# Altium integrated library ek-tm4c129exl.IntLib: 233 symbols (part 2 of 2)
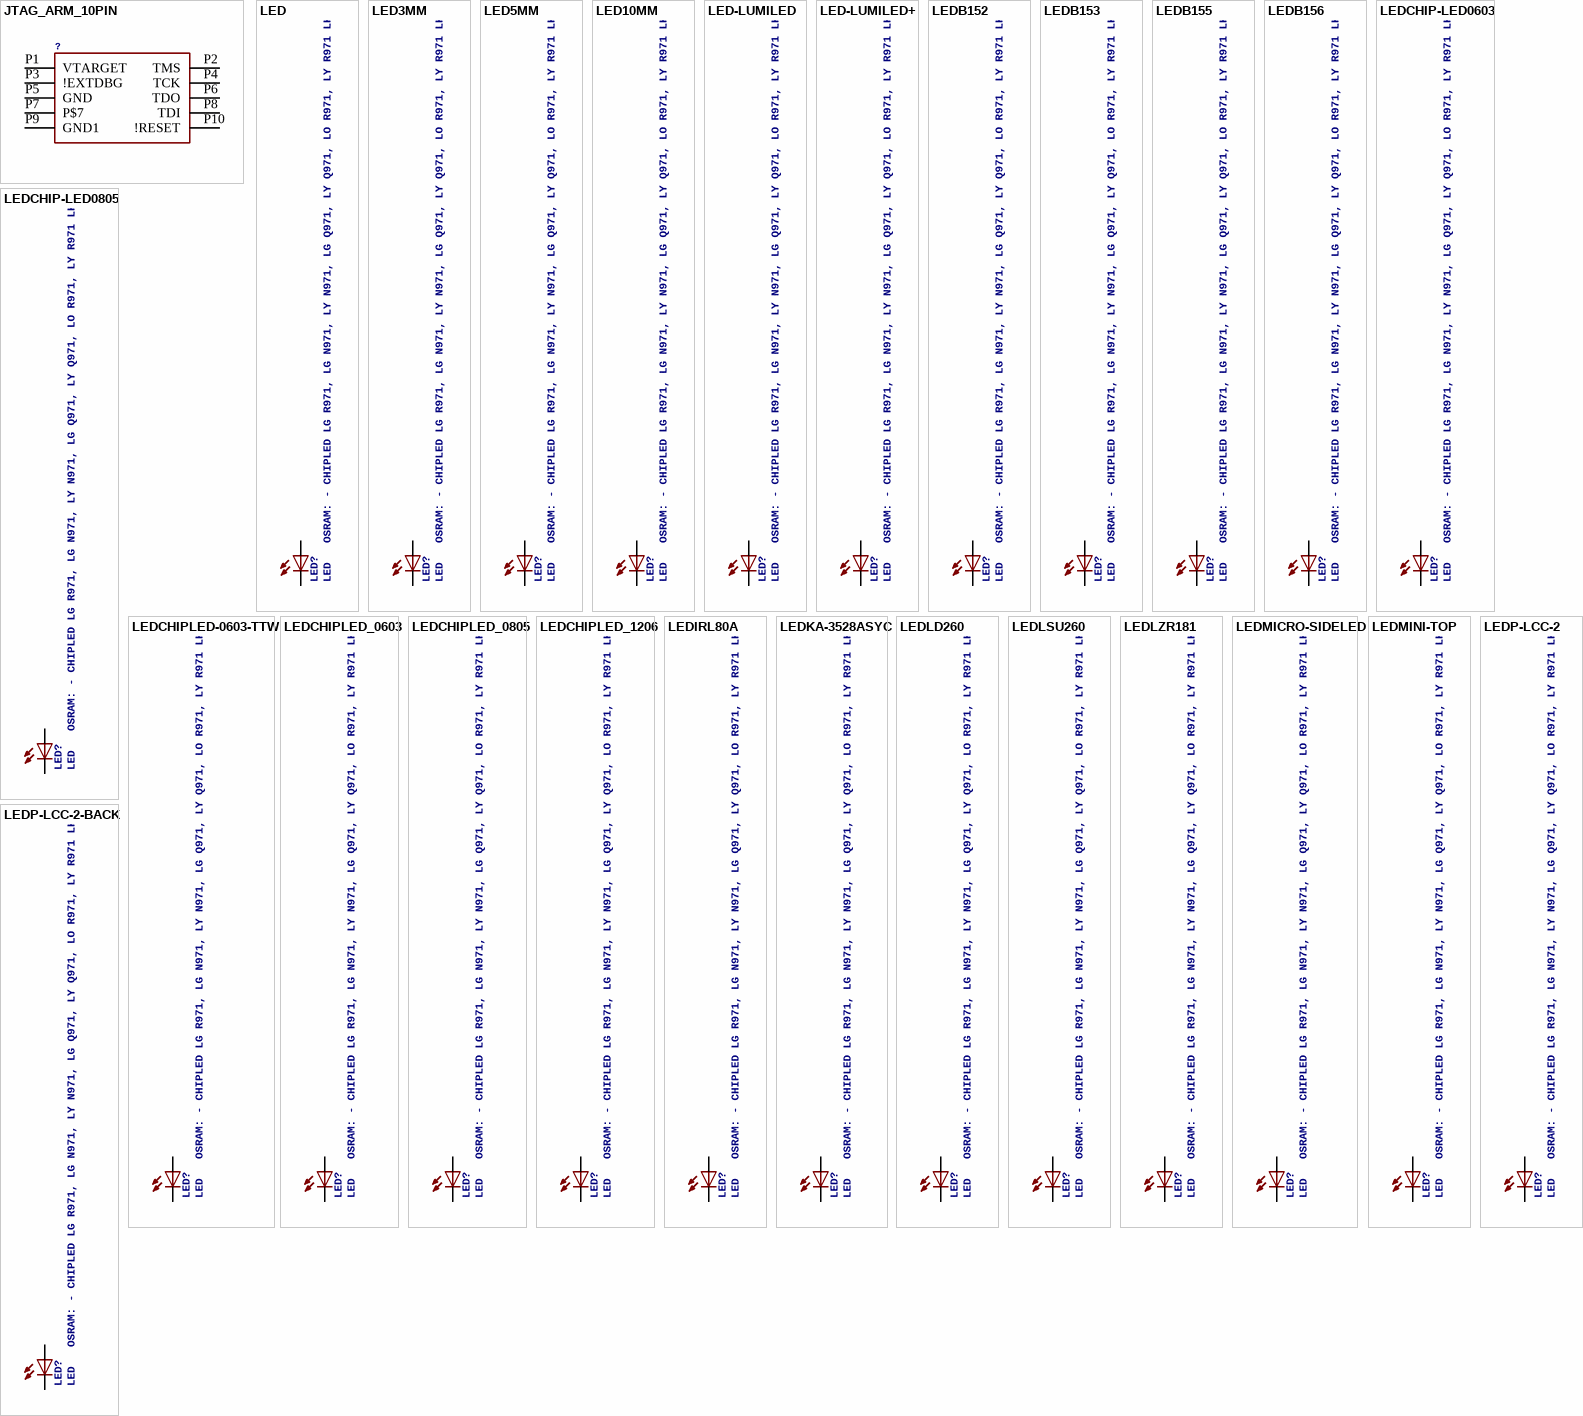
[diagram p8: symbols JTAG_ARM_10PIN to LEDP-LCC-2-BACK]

## LEDMICRO-SIDELED
designator LED?, comment LED   OSRAM: - CHIPLED LG R971, LG N971, LY N971, LG Q971, LY Q971, LO R971, LY R971 LH N974, LH R974 LS Q976, LO Q976, LY Q976 LO Q996 - Hyper CHIPLED LW Q18S LB Q993, LB Q99A, LB R99A - SideLED LS A670, LO A670, LY A670, LG A670, LP A670 LB A673, LV A673, LT A673, LW A673 LH A674 LY A675 LS A676, LA A676, LO A676, LY A676, LW A676 LS A679, LY A679, LG A679 -  Hyper Micro SIDELEDÂ® LS Y876, LA Y876, LO Y876, LY Y876 LT Y87S - SmartLED LW L88C, LW L88S LB L89C, LB L89S, LG L890 LS L89K, LO L89K, LY L89K LS L896, LA L896, LO L896, LY L896 - TOPLED LS T670, LO T670, LY T670, LG T670, LP T670 LSG T670, LSP T670, LSY T670, LOP T670, LYG T670 LG T671, LOG T671, LSG T671 LB T673, LV T673, LT T673, LW T673 LH T674 LS T676, LA T676, LO T676, LY T676, LB T676, LH T676, LSB T676, LW T676 LB T67C, LV T67C, LT T67C, LS T67K, LO T67K, LY T67K, LW E67C LS E67B, LA E67B, LO E67B, LY E67B, LB E67C, LV E67C, LT E67C LW T67C LS T679, LY T679, LG T679 LS T770, LO T770, LY T770, LG T770, LP T770 LB T773, LV T773, LT T773, LW T773 LH T774 LS E675, LA E675, LY E675, LS T675 LS T776, LA T776, LO T776, LY T776, LB T776 LHGB T686 LT T68C, LB T68C - Hyper Mini TOPLEDÂ® LB M676 - Mini TOPLED SantanaÂ® LG M470 LS M47K, LO M47K, LY M47K    Source: http://www.osram.convergy.de   LUXEON: - LUMILEDÂ® LXK2-PW12-R00, LXK2-PW12-S00, LXK2-PW14-U00, LXK2-PW14-V00 LXK2-PM12-R00, LXK2-PM12-S00, LXK2-PM14-U00 LXK2-PE12-Q00, LXK2-PE12-R00, LXK2-PE12-S00, LXK2-PE14-T00, LXK2-PE14-U00 LXK2-PB12-K00, LXK2-PB12-L00, LXK2-PB12-M00, LXK2-PB14-N00, LXK2-PB14-P00, LXK2-PB14-Q00 LXK2-PR12-L00, LXK2-PR12-M00, LXK2-PR14-Q00, LXK2-PR14-R00 LXK2-PD12-Q00, LXK2-PD12-R00, LXK2-PD12-S00 LXK2-PH12-R00, LXK2-PH12-S00 LXK2-PL12-P00, LXK2-PL12-Q00, LXK2-PL12-R00    Source: www.luxeon.com   KINGBRIGHT:   KA-3528ASYC Source: www.kingbright.com
footprint MICRO-SIDELED
pins: A, C

## LEDMINI-TOP
designator LED?, comment LED   OSRAM: - CHIPLED LG R971, LG N971, LY N971, LG Q971, LY Q971, LO R971, LY R971 LH N974, LH R974 LS Q976, LO Q976, LY Q976 LO Q996 - Hyper CHIPLED LW Q18S LB Q993, LB Q99A, LB R99A - SideLED LS A670, LO A670, LY A670, LG A670, LP A670 LB A673, LV A673, LT A673, LW A673 LH A674 LY A675 LS A676, LA A676, LO A676, LY A676, LW A676 LS A679, LY A679, LG A679 -  Hyper Micro SIDELEDÂ® LS Y876, LA Y876, LO Y876, LY Y876 LT Y87S - SmartLED LW L88C, LW L88S LB L89C, LB L89S, LG L890 LS L89K, LO L89K, LY L89K LS L896, LA L896, LO L896, LY L896 - TOPLED LS T670, LO T670, LY T670, LG T670, LP T670 LSG T670, LSP T670, LSY T670, LOP T670, LYG T670 LG T671, LOG T671, LSG T671 LB T673, LV T673, LT T673, LW T673 LH T674 LS T676, LA T676, LO T676, LY T676, LB T676, LH T676, LSB T676, LW T676 LB T67C, LV T67C, LT T67C, LS T67K, LO T67K, LY T67K, LW E67C LS E67B, LA E67B, LO E67B, LY E67B, LB E67C, LV E67C, LT E67C LW T67C LS T679, LY T679, LG T679 LS T770, LO T770, LY T770, LG T770, LP T770 LB T773, LV T773, LT T773, LW T773 LH T774 LS E675, LA E675, LY E675, LS T675 LS T776, LA T776, LO T776, LY T776, LB T776 LHGB T686 LT T68C, LB T68C - Hyper Mini TOPLEDÂ® LB M676 - Mini TOPLED SantanaÂ® LG M470 LS M47K, LO M47K, LY M47K    Source: http://www.osram.convergy.de   LUXEON: - LUMILEDÂ® LXK2-PW12-R00, LXK2-PW12-S00, LXK2-PW14-U00, LXK2-PW14-V00 LXK2-PM12-R00, LXK2-PM12-S00, LXK2-PM14-U00 LXK2-PE12-Q00, LXK2-PE12-R00, LXK2-PE12-S00, LXK2-PE14-T00, LXK2-PE14-U00 LXK2-PB12-K00, LXK2-PB12-L00, LXK2-PB12-M00, LXK2-PB14-N00, LXK2-PB14-P00, LXK2-PB14-Q00 LXK2-PR12-L00, LXK2-PR12-M00, LXK2-PR14-Q00, LXK2-PR14-R00 LXK2-PD12-Q00, LXK2-PD12-R00, LXK2-PD12-S00 LXK2-PH12-R00, LXK2-PH12-S00 LXK2-PL12-P00, LXK2-PL12-Q00, LXK2-PL12-R00    Source: www.luxeon.com   KINGBRIGHT:   KA-3528ASYC Source: www.kingbright.com
footprint OSRAM-MINI-TOP-LED
pins: A, C

## LEDP-LCC-2
designator LED?, comment LED   OSRAM: - CHIPLED LG R971, LG N971, LY N971, LG Q971, LY Q971, LO R971, LY R971 LH N974, LH R974 LS Q976, LO Q976, LY Q976 LO Q996 - Hyper CHIPLED LW Q18S LB Q993, LB Q99A, LB R99A - SideLED LS A670, LO A670, LY A670, LG A670, LP A670 LB A673, LV A673, LT A673, LW A673 LH A674 LY A675 LS A676, LA A676, LO A676, LY A676, LW A676 LS A679, LY A679, LG A679 -  Hyper Micro SIDELEDÂ® LS Y876, LA Y876, LO Y876, LY Y876 LT Y87S - SmartLED LW L88C, LW L88S LB L89C, LB L89S, LG L890 LS L89K, LO L89K, LY L89K LS L896, LA L896, LO L896, LY L896 - TOPLED LS T670, LO T670, LY T670, LG T670, LP T670 LSG T670, LSP T670, LSY T670, LOP T670, LYG T670 LG T671, LOG T671, LSG T671 LB T673, LV T673, LT T673, LW T673 LH T674 LS T676, LA T676, LO T676, LY T676, LB T676, LH T676, LSB T676, LW T676 LB T67C, LV T67C, LT T67C, LS T67K, LO T67K, LY T67K, LW E67C LS E67B, LA E67B, LO E67B, LY E67B, LB E67C, LV E67C, LT E67C LW T67C LS T679, LY T679, LG T679 LS T770, LO T770, LY T770, LG T770, LP T770 LB T773, LV T773, LT T773, LW T773 LH T774 LS E675, LA E675, LY E675, LS T675 LS T776, LA T776, LO T776, LY T776, LB T776 LHGB T686 LT T68C, LB T68C - Hyper Mini TOPLEDÂ® LB M676 - Mini TOPLED SantanaÂ® LG M470 LS M47K, LO M47K, LY M47K    Source: http://www.osram.convergy.de   LUXEON: - LUMILEDÂ® LXK2-PW12-R00, LXK2-PW12-S00, LXK2-PW14-U00, LXK2-PW14-V00 LXK2-PM12-R00, LXK2-PM12-S00, LXK2-PM14-U00 LXK2-PE12-Q00, LXK2-PE12-R00, LXK2-PE12-S00, LXK2-PE14-T00, LXK2-PE14-U00 LXK2-PB12-K00, LXK2-PB12-L00, LXK2-PB12-M00, LXK2-PB14-N00, LXK2-PB14-P00, LXK2-PB14-Q00 LXK2-PR12-L00, LXK2-PR12-M00, LXK2-PR14-Q00, LXK2-PR14-R00 LXK2-PD12-Q00, LXK2-PD12-R00, LXK2-PD12-S00 LXK2-PH12-R00, LXK2-PH12-S00 LXK2-PL12-P00, LXK2-PL12-Q00, LXK2-PL12-R00    Source: www.luxeon.com   KINGBRIGHT:   KA-3528ASYC Source: www.kingbright.com
footprint P-LCC-2
pins: A, C

## LEDP-LCC-2-BACK
designator LED?, comment LED   OSRAM: - CHIPLED LG R971, LG N971, LY N971, LG Q971, LY Q971, LO R971, LY R971 LH N974, LH R974 LS Q976, LO Q976, LY Q976 LO Q996 - Hyper CHIPLED LW Q18S LB Q993, LB Q99A, LB R99A - SideLED LS A670, LO A670, LY A670, LG A670, LP A670 LB A673, LV A673, LT A673, LW A673 LH A674 LY A675 LS A676, LA A676, LO A676, LY A676, LW A676 LS A679, LY A679, LG A679 -  Hyper Micro SIDELEDÂ® LS Y876, LA Y876, LO Y876, LY Y876 LT Y87S - SmartLED LW L88C, LW L88S LB L89C, LB L89S, LG L890 LS L89K, LO L89K, LY L89K LS L896, LA L896, LO L896, LY L896 - TOPLED LS T670, LO T670, LY T670, LG T670, LP T670 LSG T670, LSP T670, LSY T670, LOP T670, LYG T670 LG T671, LOG T671, LSG T671 LB T673, LV T673, LT T673, LW T673 LH T674 LS T676, LA T676, LO T676, LY T676, LB T676, LH T676, LSB T676, LW T676 LB T67C, LV T67C, LT T67C, LS T67K, LO T67K, LY T67K, LW E67C LS E67B, LA E67B, LO E67B, LY E67B, LB E67C, LV E67C, LT E67C LW T67C LS T679, LY T679, LG T679 LS T770, LO T770, LY T770, LG T770, LP T770 LB T773, LV T773, LT T773, LW T773 LH T774 LS E675, LA E675, LY E675, LS T675 LS T776, LA T776, LO T776, LY T776, LB T776 LHGB T686 LT T68C, LB T68C - Hyper Mini TOPLEDÂ® LB M676 - Mini TOPLED SantanaÂ® LG M470 LS M47K, LO M47K, LY M47K    Source: http://www.osram.convergy.de   LUXEON: - LUMILEDÂ® LXK2-PW12-R00, LXK2-PW12-S00, LXK2-PW14-U00, LXK2-PW14-V00 LXK2-PM12-R00, LXK2-PM12-S00, LXK2-PM14-U00 LXK2-PE12-Q00, LXK2-PE12-R00, LXK2-PE12-S00, LXK2-PE14-T00, LXK2-PE14-U00 LXK2-PB12-K00, LXK2-PB12-L00, LXK2-PB12-M00, LXK2-PB14-N00, LXK2-PB14-P00, LXK2-PB14-Q00 LXK2-PR12-L00, LXK2-PR12-M00, LXK2-PR14-Q00, LXK2-PR14-R00 LXK2-PD12-Q00, LXK2-PD12-R00, LXK2-PD12-S00 LXK2-PH12-R00, LXK2-PH12-S00 LXK2-PL12-P00, LXK2-PL12-Q00, LXK2-PL12-R00    Source: www.luxeon.com   KINGBRIGHT:   KA-3528ASYC Source: www.kingbright.com
footprint P-LCC-2-TOPLED-RG
pins: A, C

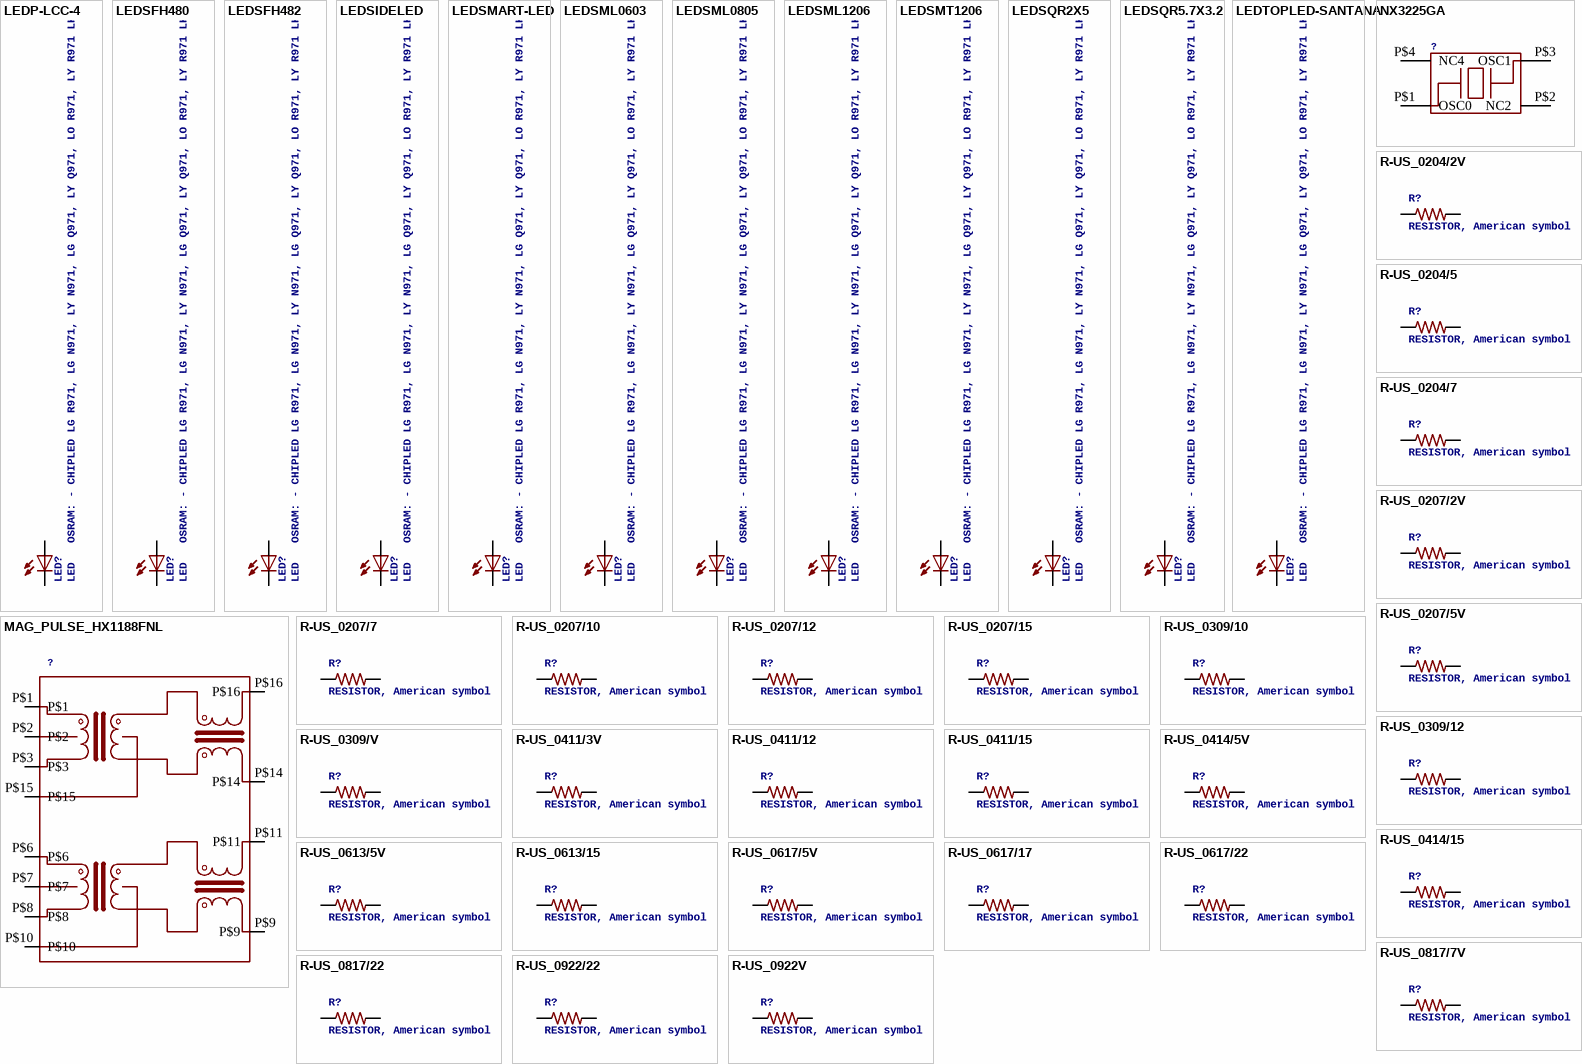
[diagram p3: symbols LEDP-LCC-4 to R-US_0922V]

## LEDP-LCC-4
designator LED?, comment LED   OSRAM: - CHIPLED LG R971, LG N971, LY N971, LG Q971, LY Q971, LO R971, LY R971 LH N974, LH R974 LS Q976, LO Q976, LY Q976 LO Q996 - Hyper CHIPLED LW Q18S LB Q993, LB Q99A, LB R99A - SideLED LS A670, LO A670, LY A670, LG A670, LP A670 LB A673, LV A673, LT A673, LW A673 LH A674 LY A675 LS A676, LA A676, LO A676, LY A676, LW A676 LS A679, LY A679, LG A679 -  Hyper Micro SIDELEDÂ® LS Y876, LA Y876, LO Y876, LY Y876 LT Y87S - SmartLED LW L88C, LW L88S LB L89C, LB L89S, LG L890 LS L89K, LO L89K, LY L89K LS L896, LA L896, LO L896, LY L896 - TOPLED LS T670, LO T670, LY T670, LG T670, LP T670 LSG T670, LSP T670, LSY T670, LOP T670, LYG T670 LG T671, LOG T671, LSG T671 LB T673, LV T673, LT T673, LW T673 LH T674 LS T676, LA T676, LO T676, LY T676, LB T676, LH T676, LSB T676, LW T676 LB T67C, LV T67C, LT T67C, LS T67K, LO T67K, LY T67K, LW E67C LS E67B, LA E67B, LO E67B, LY E67B, LB E67C, LV E67C, LT E67C LW T67C LS T679, LY T679, LG T679 LS T770, LO T770, LY T770, LG T770, LP T770 LB T773, LV T773, LT T773, LW T773 LH T774 LS E675, LA E675, LY E675, LS T675 LS T776, LA T776, LO T776, LY T776, LB T776 LHGB T686 LT T68C, LB T68C - Hyper Mini TOPLEDÂ® LB M676 - Mini TOPLED SantanaÂ® LG M470 LS M47K, LO M47K, LY M47K    Source: http://www.osram.convergy.de   LUXEON: - LUMILEDÂ® LXK2-PW12-R00, LXK2-PW12-S00, LXK2-PW14-U00, LXK2-PW14-V00 LXK2-PM12-R00, LXK2-PM12-S00, LXK2-PM14-U00 LXK2-PE12-Q00, LXK2-PE12-R00, LXK2-PE12-S00, LXK2-PE14-T00, LXK2-PE14-U00 LXK2-PB12-K00, LXK2-PB12-L00, LXK2-PB12-M00, LXK2-PB14-N00, LXK2-PB14-P00, LXK2-PB14-Q00 LXK2-PR12-L00, LXK2-PR12-M00, LXK2-PR14-Q00, LXK2-PR14-R00 LXK2-PD12-Q00, LXK2-PD12-R00, LXK2-PD12-S00 LXK2-PH12-R00, LXK2-PH12-S00 LXK2-PL12-P00, LXK2-PL12-Q00, LXK2-PL12-R00    Source: www.luxeon.com   KINGBRIGHT:   KA-3528ASYC Source: www.kingbright.com
footprint P-LCC-4
pins: A, C@4 C

## LEDSFH480
designator LED?, comment LED   OSRAM: - CHIPLED LG R971, LG N971, LY N971, LG Q971, LY Q971, LO R971, LY R971 LH N974, LH R974 LS Q976, LO Q976, LY Q976 LO Q996 - Hyper CHIPLED LW Q18S LB Q993, LB Q99A, LB R99A - SideLED LS A670, LO A670, LY A670, LG A670, LP A670 LB A673, LV A673, LT A673, LW A673 LH A674 LY A675 LS A676, LA A676, LO A676, LY A676, LW A676 LS A679, LY A679, LG A679 -  Hyper Micro SIDELEDÂ® LS Y876, LA Y876, LO Y876, LY Y876 LT Y87S - SmartLED LW L88C, LW L88S LB L89C, LB L89S, LG L890 LS L89K, LO L89K, LY L89K LS L896, LA L896, LO L896, LY L896 - TOPLED LS T670, LO T670, LY T670, LG T670, LP T670 LSG T670, LSP T670, LSY T670, LOP T670, LYG T670 LG T671, LOG T671, LSG T671 LB T673, LV T673, LT T673, LW T673 LH T674 LS T676, LA T676, LO T676, LY T676, LB T676, LH T676, LSB T676, LW T676 LB T67C, LV T67C, LT T67C, LS T67K, LO T67K, LY T67K, LW E67C LS E67B, LA E67B, LO E67B, LY E67B, LB E67C, LV E67C, LT E67C LW T67C LS T679, LY T679, LG T679 LS T770, LO T770, LY T770, LG T770, LP T770 LB T773, LV T773, LT T773, LW T773 LH T774 LS E675, LA E675, LY E675, LS T675 LS T776, LA T776, LO T776, LY T776, LB T776 LHGB T686 LT T68C, LB T68C - Hyper Mini TOPLEDÂ® LB M676 - Mini TOPLED SantanaÂ® LG M470 LS M47K, LO M47K, LY M47K    Source: http://www.osram.convergy.de   LUXEON: - LUMILEDÂ® LXK2-PW12-R00, LXK2-PW12-S00, LXK2-PW14-U00, LXK2-PW14-V00 LXK2-PM12-R00, LXK2-PM12-S00, LXK2-PM14-U00 LXK2-PE12-Q00, LXK2-PE12-R00, LXK2-PE12-S00, LXK2-PE14-T00, LXK2-PE14-U00 LXK2-PB12-K00, LXK2-PB12-L00, LXK2-PB12-M00, LXK2-PB14-N00, LXK2-PB14-P00, LXK2-PB14-Q00 LXK2-PR12-L00, LXK2-PR12-M00, LXK2-PR14-Q00, LXK2-PR14-R00 LXK2-PD12-Q00, LXK2-PD12-R00, LXK2-PD12-S00 LXK2-PH12-R00, LXK2-PH12-S00 LXK2-PL12-P00, LXK2-PL12-Q00, LXK2-PL12-R00    Source: www.luxeon.com   KINGBRIGHT:   KA-3528ASYC Source: www.kingbright.com
footprint SFH480
pins: A, K C

## LEDSFH482
designator LED?, comment LED   OSRAM: - CHIPLED LG R971, LG N971, LY N971, LG Q971, LY Q971, LO R971, LY R971 LH N974, LH R974 LS Q976, LO Q976, LY Q976 LO Q996 - Hyper CHIPLED LW Q18S LB Q993, LB Q99A, LB R99A - SideLED LS A670, LO A670, LY A670, LG A670, LP A670 LB A673, LV A673, LT A673, LW A673 LH A674 LY A675 LS A676, LA A676, LO A676, LY A676, LW A676 LS A679, LY A679, LG A679 -  Hyper Micro SIDELEDÂ® LS Y876, LA Y876, LO Y876, LY Y876 LT Y87S - SmartLED LW L88C, LW L88S LB L89C, LB L89S, LG L890 LS L89K, LO L89K, LY L89K LS L896, LA L896, LO L896, LY L896 - TOPLED LS T670, LO T670, LY T670, LG T670, LP T670 LSG T670, LSP T670, LSY T670, LOP T670, LYG T670 LG T671, LOG T671, LSG T671 LB T673, LV T673, LT T673, LW T673 LH T674 LS T676, LA T676, LO T676, LY T676, LB T676, LH T676, LSB T676, LW T676 LB T67C, LV T67C, LT T67C, LS T67K, LO T67K, LY T67K, LW E67C LS E67B, LA E67B, LO E67B, LY E67B, LB E67C, LV E67C, LT E67C LW T67C LS T679, LY T679, LG T679 LS T770, LO T770, LY T770, LG T770, LP T770 LB T773, LV T773, LT T773, LW T773 LH T774 LS E675, LA E675, LY E675, LS T675 LS T776, LA T776, LO T776, LY T776, LB T776 LHGB T686 LT T68C, LB T68C - Hyper Mini TOPLEDÂ® LB M676 - Mini TOPLED SantanaÂ® LG M470 LS M47K, LO M47K, LY M47K    Source: http://www.osram.convergy.de   LUXEON: - LUMILEDÂ® LXK2-PW12-R00, LXK2-PW12-S00, LXK2-PW14-U00, LXK2-PW14-V00 LXK2-PM12-R00, LXK2-PM12-S00, LXK2-PM14-U00 LXK2-PE12-Q00, LXK2-PE12-R00, LXK2-PE12-S00, LXK2-PE14-T00, LXK2-PE14-U00 LXK2-PB12-K00, LXK2-PB12-L00, LXK2-PB12-M00, LXK2-PB14-N00, LXK2-PB14-P00, LXK2-PB14-Q00 LXK2-PR12-L00, LXK2-PR12-M00, LXK2-PR14-Q00, LXK2-PR14-R00 LXK2-PD12-Q00, LXK2-PD12-R00, LXK2-PD12-S00 LXK2-PH12-R00, LXK2-PH12-S00 LXK2-PL12-P00, LXK2-PL12-Q00, LXK2-PL12-R00    Source: www.luxeon.com   KINGBRIGHT:   KA-3528ASYC Source: www.kingbright.com
footprint SFH482
pins: A, K C

## LEDSIDELED
designator LED?, comment LED   OSRAM: - CHIPLED LG R971, LG N971, LY N971, LG Q971, LY Q971, LO R971, LY R971 LH N974, LH R974 LS Q976, LO Q976, LY Q976 LO Q996 - Hyper CHIPLED LW Q18S LB Q993, LB Q99A, LB R99A - SideLED LS A670, LO A670, LY A670, LG A670, LP A670 LB A673, LV A673, LT A673, LW A673 LH A674 LY A675 LS A676, LA A676, LO A676, LY A676, LW A676 LS A679, LY A679, LG A679 -  Hyper Micro SIDELEDÂ® LS Y876, LA Y876, LO Y876, LY Y876 LT Y87S - SmartLED LW L88C, LW L88S LB L89C, LB L89S, LG L890 LS L89K, LO L89K, LY L89K LS L896, LA L896, LO L896, LY L896 - TOPLED LS T670, LO T670, LY T670, LG T670, LP T670 LSG T670, LSP T670, LSY T670, LOP T670, LYG T670 LG T671, LOG T671, LSG T671 LB T673, LV T673, LT T673, LW T673 LH T674 LS T676, LA T676, LO T676, LY T676, LB T676, LH T676, LSB T676, LW T676 LB T67C, LV T67C, LT T67C, LS T67K, LO T67K, LY T67K, LW E67C LS E67B, LA E67B, LO E67B, LY E67B, LB E67C, LV E67C, LT E67C LW T67C LS T679, LY T679, LG T679 LS T770, LO T770, LY T770, LG T770, LP T770 LB T773, LV T773, LT T773, LW T773 LH T774 LS E675, LA E675, LY E675, LS T675 LS T776, LA T776, LO T776, LY T776, LB T776 LHGB T686 LT T68C, LB T68C - Hyper Mini TOPLEDÂ® LB M676 - Mini TOPLED SantanaÂ® LG M470 LS M47K, LO M47K, LY M47K    Source: http://www.osram.convergy.de   LUXEON: - LUMILEDÂ® LXK2-PW12-R00, LXK2-PW12-S00, LXK2-PW14-U00, LXK2-PW14-V00 LXK2-PM12-R00, LXK2-PM12-S00, LXK2-PM14-U00 LXK2-PE12-Q00, LXK2-PE12-R00, LXK2-PE12-S00, LXK2-PE14-T00, LXK2-PE14-U00 LXK2-PB12-K00, LXK2-PB12-L00, LXK2-PB12-M00, LXK2-PB14-N00, LXK2-PB14-P00, LXK2-PB14-Q00 LXK2-PR12-L00, LXK2-PR12-M00, LXK2-PR14-Q00, LXK2-PR14-R00 LXK2-PD12-Q00, LXK2-PD12-R00, LXK2-PD12-S00 LXK2-PH12-R00, LXK2-PH12-S00 LXK2-PL12-P00, LXK2-PL12-Q00, LXK2-PL12-R00    Source: www.luxeon.com   KINGBRIGHT:   KA-3528ASYC Source: www.kingbright.com
footprint OSRAM-SIDELED
pins: A, C

## LEDSMART-LED
designator LED?, comment LED   OSRAM: - CHIPLED LG R971, LG N971, LY N971, LG Q971, LY Q971, LO R971, LY R971 LH N974, LH R974 LS Q976, LO Q976, LY Q976 LO Q996 - Hyper CHIPLED LW Q18S LB Q993, LB Q99A, LB R99A - SideLED LS A670, LO A670, LY A670, LG A670, LP A670 LB A673, LV A673, LT A673, LW A673 LH A674 LY A675 LS A676, LA A676, LO A676, LY A676, LW A676 LS A679, LY A679, LG A679 -  Hyper Micro SIDELEDÂ® LS Y876, LA Y876, LO Y876, LY Y876 LT Y87S - SmartLED LW L88C, LW L88S LB L89C, LB L89S, LG L890 LS L89K, LO L89K, LY L89K LS L896, LA L896, LO L896, LY L896 - TOPLED LS T670, LO T670, LY T670, LG T670, LP T670 LSG T670, LSP T670, LSY T670, LOP T670, LYG T670 LG T671, LOG T671, LSG T671 LB T673, LV T673, LT T673, LW T673 LH T674 LS T676, LA T676, LO T676, LY T676, LB T676, LH T676, LSB T676, LW T676 LB T67C, LV T67C, LT T67C, LS T67K, LO T67K, LY T67K, LW E67C LS E67B, LA E67B, LO E67B, LY E67B, LB E67C, LV E67C, LT E67C LW T67C LS T679, LY T679, LG T679 LS T770, LO T770, LY T770, LG T770, LP T770 LB T773, LV T773, LT T773, LW T773 LH T774 LS E675, LA E675, LY E675, LS T675 LS T776, LA T776, LO T776, LY T776, LB T776 LHGB T686 LT T68C, LB T68C - Hyper Mini TOPLEDÂ® LB M676 - Mini TOPLED SantanaÂ® LG M470 LS M47K, LO M47K, LY M47K    Source: http://www.osram.convergy.de   LUXEON: - LUMILEDÂ® LXK2-PW12-R00, LXK2-PW12-S00, LXK2-PW14-U00, LXK2-PW14-V00 LXK2-PM12-R00, LXK2-PM12-S00, LXK2-PM14-U00 LXK2-PE12-Q00, LXK2-PE12-R00, LXK2-PE12-S00, LXK2-PE14-T00, LXK2-PE14-U00 LXK2-PB12-K00, LXK2-PB12-L00, LXK2-PB12-M00, LXK2-PB14-N00, LXK2-PB14-P00, LXK2-PB14-Q00 LXK2-PR12-L00, LXK2-PR12-M00, LXK2-PR14-Q00, LXK2-PR14-R00 LXK2-PD12-Q00, LXK2-PD12-R00, LXK2-PD12-S00 LXK2-PH12-R00, LXK2-PH12-S00 LXK2-PL12-P00, LXK2-PL12-Q00, LXK2-PL12-R00    Source: www.luxeon.com   KINGBRIGHT:   KA-3528ASYC Source: www.kingbright.com
footprint SMART-LED
pins: A, B C

## LEDSML0603
designator LED?, comment LED   OSRAM: - CHIPLED LG R971, LG N971, LY N971, LG Q971, LY Q971, LO R971, LY R971 LH N974, LH R974 LS Q976, LO Q976, LY Q976 LO Q996 - Hyper CHIPLED LW Q18S LB Q993, LB Q99A, LB R99A - SideLED LS A670, LO A670, LY A670, LG A670, LP A670 LB A673, LV A673, LT A673, LW A673 LH A674 LY A675 LS A676, LA A676, LO A676, LY A676, LW A676 LS A679, LY A679, LG A679 -  Hyper Micro SIDELEDÂ® LS Y876, LA Y876, LO Y876, LY Y876 LT Y87S - SmartLED LW L88C, LW L88S LB L89C, LB L89S, LG L890 LS L89K, LO L89K, LY L89K LS L896, LA L896, LO L896, LY L896 - TOPLED LS T670, LO T670, LY T670, LG T670, LP T670 LSG T670, LSP T670, LSY T670, LOP T670, LYG T670 LG T671, LOG T671, LSG T671 LB T673, LV T673, LT T673, LW T673 LH T674 LS T676, LA T676, LO T676, LY T676, LB T676, LH T676, LSB T676, LW T676 LB T67C, LV T67C, LT T67C, LS T67K, LO T67K, LY T67K, LW E67C LS E67B, LA E67B, LO E67B, LY E67B, LB E67C, LV E67C, LT E67C LW T67C LS T679, LY T679, LG T679 LS T770, LO T770, LY T770, LG T770, LP T770 LB T773, LV T773, LT T773, LW T773 LH T774 LS E675, LA E675, LY E675, LS T675 LS T776, LA T776, LO T776, LY T776, LB T776 LHGB T686 LT T68C, LB T68C - Hyper Mini TOPLEDÂ® LB M676 - Mini TOPLED SantanaÂ® LG M470 LS M47K, LO M47K, LY M47K    Source: http://www.osram.convergy.de   LUXEON: - LUMILEDÂ® LXK2-PW12-R00, LXK2-PW12-S00, LXK2-PW14-U00, LXK2-PW14-V00 LXK2-PM12-R00, LXK2-PM12-S00, LXK2-PM14-U00 LXK2-PE12-Q00, LXK2-PE12-R00, LXK2-PE12-S00, LXK2-PE14-T00, LXK2-PE14-U00 LXK2-PB12-K00, LXK2-PB12-L00, LXK2-PB12-M00, LXK2-PB14-N00, LXK2-PB14-P00, LXK2-PB14-Q00 LXK2-PR12-L00, LXK2-PR12-M00, LXK2-PR14-Q00, LXK2-PR14-R00 LXK2-PD12-Q00, LXK2-PD12-R00, LXK2-PD12-S00 LXK2-PH12-R00, LXK2-PH12-S00 LXK2-PL12-P00, LXK2-PL12-Q00, LXK2-PL12-R00    Source: www.luxeon.com   KINGBRIGHT:   KA-3528ASYC Source: www.kingbright.com
footprint SML0603
pins: A, C

## LEDSML0805
designator LED?, comment LED   OSRAM: - CHIPLED LG R971, LG N971, LY N971, LG Q971, LY Q971, LO R971, LY R971 LH N974, LH R974 LS Q976, LO Q976, LY Q976 LO Q996 - Hyper CHIPLED LW Q18S LB Q993, LB Q99A, LB R99A - SideLED LS A670, LO A670, LY A670, LG A670, LP A670 LB A673, LV A673, LT A673, LW A673 LH A674 LY A675 LS A676, LA A676, LO A676, LY A676, LW A676 LS A679, LY A679, LG A679 -  Hyper Micro SIDELEDÂ® LS Y876, LA Y876, LO Y876, LY Y876 LT Y87S - SmartLED LW L88C, LW L88S LB L89C, LB L89S, LG L890 LS L89K, LO L89K, LY L89K LS L896, LA L896, LO L896, LY L896 - TOPLED LS T670, LO T670, LY T670, LG T670, LP T670 LSG T670, LSP T670, LSY T670, LOP T670, LYG T670 LG T671, LOG T671, LSG T671 LB T673, LV T673, LT T673, LW T673 LH T674 LS T676, LA T676, LO T676, LY T676, LB T676, LH T676, LSB T676, LW T676 LB T67C, LV T67C, LT T67C, LS T67K, LO T67K, LY T67K, LW E67C LS E67B, LA E67B, LO E67B, LY E67B, LB E67C, LV E67C, LT E67C LW T67C LS T679, LY T679, LG T679 LS T770, LO T770, LY T770, LG T770, LP T770 LB T773, LV T773, LT T773, LW T773 LH T774 LS E675, LA E675, LY E675, LS T675 LS T776, LA T776, LO T776, LY T776, LB T776 LHGB T686 LT T68C, LB T68C - Hyper Mini TOPLEDÂ® LB M676 - Mini TOPLED SantanaÂ® LG M470 LS M47K, LO M47K, LY M47K    Source: http://www.osram.convergy.de   LUXEON: - LUMILEDÂ® LXK2-PW12-R00, LXK2-PW12-S00, LXK2-PW14-U00, LXK2-PW14-V00 LXK2-PM12-R00, LXK2-PM12-S00, LXK2-PM14-U00 LXK2-PE12-Q00, LXK2-PE12-R00, LXK2-PE12-S00, LXK2-PE14-T00, LXK2-PE14-U00 LXK2-PB12-K00, LXK2-PB12-L00, LXK2-PB12-M00, LXK2-PB14-N00, LXK2-PB14-P00, LXK2-PB14-Q00 LXK2-PR12-L00, LXK2-PR12-M00, LXK2-PR14-Q00, LXK2-PR14-R00 LXK2-PD12-Q00, LXK2-PD12-R00, LXK2-PD12-S00 LXK2-PH12-R00, LXK2-PH12-S00 LXK2-PL12-P00, LXK2-PL12-Q00, LXK2-PL12-R00    Source: www.luxeon.com   KINGBRIGHT:   KA-3528ASYC Source: www.kingbright.com
footprint SML0805
pins: A, C

## LEDSML1206
designator LED?, comment LED   OSRAM: - CHIPLED LG R971, LG N971, LY N971, LG Q971, LY Q971, LO R971, LY R971 LH N974, LH R974 LS Q976, LO Q976, LY Q976 LO Q996 - Hyper CHIPLED LW Q18S LB Q993, LB Q99A, LB R99A - SideLED LS A670, LO A670, LY A670, LG A670, LP A670 LB A673, LV A673, LT A673, LW A673 LH A674 LY A675 LS A676, LA A676, LO A676, LY A676, LW A676 LS A679, LY A679, LG A679 -  Hyper Micro SIDELEDÂ® LS Y876, LA Y876, LO Y876, LY Y876 LT Y87S - SmartLED LW L88C, LW L88S LB L89C, LB L89S, LG L890 LS L89K, LO L89K, LY L89K LS L896, LA L896, LO L896, LY L896 - TOPLED LS T670, LO T670, LY T670, LG T670, LP T670 LSG T670, LSP T670, LSY T670, LOP T670, LYG T670 LG T671, LOG T671, LSG T671 LB T673, LV T673, LT T673, LW T673 LH T674 LS T676, LA T676, LO T676, LY T676, LB T676, LH T676, LSB T676, LW T676 LB T67C, LV T67C, LT T67C, LS T67K, LO T67K, LY T67K, LW E67C LS E67B, LA E67B, LO E67B, LY E67B, LB E67C, LV E67C, LT E67C LW T67C LS T679, LY T679, LG T679 LS T770, LO T770, LY T770, LG T770, LP T770 LB T773, LV T773, LT T773, LW T773 LH T774 LS E675, LA E675, LY E675, LS T675 LS T776, LA T776, LO T776, LY T776, LB T776 LHGB T686 LT T68C, LB T68C - Hyper Mini TOPLEDÂ® LB M676 - Mini TOPLED SantanaÂ® LG M470 LS M47K, LO M47K, LY M47K    Source: http://www.osram.convergy.de   LUXEON: - LUMILEDÂ® LXK2-PW12-R00, LXK2-PW12-S00, LXK2-PW14-U00, LXK2-PW14-V00 LXK2-PM12-R00, LXK2-PM12-S00, LXK2-PM14-U00 LXK2-PE12-Q00, LXK2-PE12-R00, LXK2-PE12-S00, LXK2-PE14-T00, LXK2-PE14-U00 LXK2-PB12-K00, LXK2-PB12-L00, LXK2-PB12-M00, LXK2-PB14-N00, LXK2-PB14-P00, LXK2-PB14-Q00 LXK2-PR12-L00, LXK2-PR12-M00, LXK2-PR14-Q00, LXK2-PR14-R00 LXK2-PD12-Q00, LXK2-PD12-R00, LXK2-PD12-S00 LXK2-PH12-R00, LXK2-PH12-S00 LXK2-PL12-P00, LXK2-PL12-Q00, LXK2-PL12-R00    Source: www.luxeon.com   KINGBRIGHT:   KA-3528ASYC Source: www.kingbright.com
footprint SML1206
pins: A, C

## LEDSMT1206
designator LED?, comment LED   OSRAM: - CHIPLED LG R971, LG N971, LY N971, LG Q971, LY Q971, LO R971, LY R971 LH N974, LH R974 LS Q976, LO Q976, LY Q976 LO Q996 - Hyper CHIPLED LW Q18S LB Q993, LB Q99A, LB R99A - SideLED LS A670, LO A670, LY A670, LG A670, LP A670 LB A673, LV A673, LT A673, LW A673 LH A674 LY A675 LS A676, LA A676, LO A676, LY A676, LW A676 LS A679, LY A679, LG A679 -  Hyper Micro SIDELEDÂ® LS Y876, LA Y876, LO Y876, LY Y876 LT Y87S - SmartLED LW L88C, LW L88S LB L89C, LB L89S, LG L890 LS L89K, LO L89K, LY L89K LS L896, LA L896, LO L896, LY L896 - TOPLED LS T670, LO T670, LY T670, LG T670, LP T670 LSG T670, LSP T670, LSY T670, LOP T670, LYG T670 LG T671, LOG T671, LSG T671 LB T673, LV T673, LT T673, LW T673 LH T674 LS T676, LA T676, LO T676, LY T676, LB T676, LH T676, LSB T676, LW T676 LB T67C, LV T67C, LT T67C, LS T67K, LO T67K, LY T67K, LW E67C LS E67B, LA E67B, LO E67B, LY E67B, LB E67C, LV E67C, LT E67C LW T67C LS T679, LY T679, LG T679 LS T770, LO T770, LY T770, LG T770, LP T770 LB T773, LV T773, LT T773, LW T773 LH T774 LS E675, LA E675, LY E675, LS T675 LS T776, LA T776, LO T776, LY T776, LB T776 LHGB T686 LT T68C, LB T68C - Hyper Mini TOPLEDÂ® LB M676 - Mini TOPLED SantanaÂ® LG M470 LS M47K, LO M47K, LY M47K    Source: http://www.osram.convergy.de   LUXEON: - LUMILEDÂ® LXK2-PW12-R00, LXK2-PW12-S00, LXK2-PW14-U00, LXK2-PW14-V00 LXK2-PM12-R00, LXK2-PM12-S00, LXK2-PM14-U00 LXK2-PE12-Q00, LXK2-PE12-R00, LXK2-PE12-S00, LXK2-PE14-T00, LXK2-PE14-U00 LXK2-PB12-K00, LXK2-PB12-L00, LXK2-PB12-M00, LXK2-PB14-N00, LXK2-PB14-P00, LXK2-PB14-Q00 LXK2-PR12-L00, LXK2-PR12-M00, LXK2-PR14-Q00, LXK2-PR14-R00 LXK2-PD12-Q00, LXK2-PD12-R00, LXK2-PD12-S00 LXK2-PH12-R00, LXK2-PH12-S00 LXK2-PL12-P00, LXK2-PL12-Q00, LXK2-PL12-R00    Source: www.luxeon.com   KINGBRIGHT:   KA-3528ASYC Source: www.kingbright.com
footprint 1206
pins: A, C

## LEDSQR2X5
designator LED?, comment LED   OSRAM: - CHIPLED LG R971, LG N971, LY N971, LG Q971, LY Q971, LO R971, LY R971 LH N974, LH R974 LS Q976, LO Q976, LY Q976 LO Q996 - Hyper CHIPLED LW Q18S LB Q993, LB Q99A, LB R99A - SideLED LS A670, LO A670, LY A670, LG A670, LP A670 LB A673, LV A673, LT A673, LW A673 LH A674 LY A675 LS A676, LA A676, LO A676, LY A676, LW A676 LS A679, LY A679, LG A679 -  Hyper Micro SIDELEDÂ® LS Y876, LA Y876, LO Y876, LY Y876 LT Y87S - SmartLED LW L88C, LW L88S LB L89C, LB L89S, LG L890 LS L89K, LO L89K, LY L89K LS L896, LA L896, LO L896, LY L896 - TOPLED LS T670, LO T670, LY T670, LG T670, LP T670 LSG T670, LSP T670, LSY T670, LOP T670, LYG T670 LG T671, LOG T671, LSG T671 LB T673, LV T673, LT T673, LW T673 LH T674 LS T676, LA T676, LO T676, LY T676, LB T676, LH T676, LSB T676, LW T676 LB T67C, LV T67C, LT T67C, LS T67K, LO T67K, LY T67K, LW E67C LS E67B, LA E67B, LO E67B, LY E67B, LB E67C, LV E67C, LT E67C LW T67C LS T679, LY T679, LG T679 LS T770, LO T770, LY T770, LG T770, LP T770 LB T773, LV T773, LT T773, LW T773 LH T774 LS E675, LA E675, LY E675, LS T675 LS T776, LA T776, LO T776, LY T776, LB T776 LHGB T686 LT T68C, LB T68C - Hyper Mini TOPLEDÂ® LB M676 - Mini TOPLED SantanaÂ® LG M470 LS M47K, LO M47K, LY M47K    Source: http://www.osram.convergy.de   LUXEON: - LUMILEDÂ® LXK2-PW12-R00, LXK2-PW12-S00, LXK2-PW14-U00, LXK2-PW14-V00 LXK2-PM12-R00, LXK2-PM12-S00, LXK2-PM14-U00 LXK2-PE12-Q00, LXK2-PE12-R00, LXK2-PE12-S00, LXK2-PE14-T00, LXK2-PE14-U00 LXK2-PB12-K00, LXK2-PB12-L00, LXK2-PB12-M00, LXK2-PB14-N00, LXK2-PB14-P00, LXK2-PB14-Q00 LXK2-PR12-L00, LXK2-PR12-M00, LXK2-PR14-Q00, LXK2-PR14-R00 LXK2-PD12-Q00, LXK2-PD12-R00, LXK2-PD12-S00 LXK2-PH12-R00, LXK2-PH12-S00 LXK2-PL12-P00, LXK2-PL12-Q00, LXK2-PL12-R00    Source: www.luxeon.com   KINGBRIGHT:   KA-3528ASYC Source: www.kingbright.com
footprint LED2X5
pins: A, K C

## LEDSQR5.7X3.2
designator LED?, comment LED   OSRAM: - CHIPLED LG R971, LG N971, LY N971, LG Q971, LY Q971, LO R971, LY R971 LH N974, LH R974 LS Q976, LO Q976, LY Q976 LO Q996 - Hyper CHIPLED LW Q18S LB Q993, LB Q99A, LB R99A - SideLED LS A670, LO A670, LY A670, LG A670, LP A670 LB A673, LV A673, LT A673, LW A673 LH A674 LY A675 LS A676, LA A676, LO A676, LY A676, LW A676 LS A679, LY A679, LG A679 -  Hyper Micro SIDELEDÂ® LS Y876, LA Y876, LO Y876, LY Y876 LT Y87S - SmartLED LW L88C, LW L88S LB L89C, LB L89S, LG L890 LS L89K, LO L89K, LY L89K LS L896, LA L896, LO L896, LY L896 - TOPLED LS T670, LO T670, LY T670, LG T670, LP T670 LSG T670, LSP T670, LSY T670, LOP T670, LYG T670 LG T671, LOG T671, LSG T671 LB T673, LV T673, LT T673, LW T673 LH T674 LS T676, LA T676, LO T676, LY T676, LB T676, LH T676, LSB T676, LW T676 LB T67C, LV T67C, LT T67C, LS T67K, LO T67K, LY T67K, LW E67C LS E67B, LA E67B, LO E67B, LY E67B, LB E67C, LV E67C, LT E67C LW T67C LS T679, LY T679, LG T679 LS T770, LO T770, LY T770, LG T770, LP T770 LB T773, LV T773, LT T773, LW T773 LH T774 LS E675, LA E675, LY E675, LS T675 LS T776, LA T776, LO T776, LY T776, LB T776 LHGB T686 LT T68C, LB T68C - Hyper Mini TOPLEDÂ® LB M676 - Mini TOPLED SantanaÂ® LG M470 LS M47K, LO M47K, LY M47K    Source: http://www.osram.convergy.de   LUXEON: - LUMILEDÂ® LXK2-PW12-R00, LXK2-PW12-S00, LXK2-PW14-U00, LXK2-PW14-V00 LXK2-PM12-R00, LXK2-PM12-S00, LXK2-PM14-U00 LXK2-PE12-Q00, LXK2-PE12-R00, LXK2-PE12-S00, LXK2-PE14-T00, LXK2-PE14-U00 LXK2-PB12-K00, LXK2-PB12-L00, LXK2-PB12-M00, LXK2-PB14-N00, LXK2-PB14-P00, LXK2-PB14-Q00 LXK2-PR12-L00, LXK2-PR12-M00, LXK2-PR14-Q00, LXK2-PR14-R00 LXK2-PD12-Q00, LXK2-PD12-R00, LXK2-PD12-S00 LXK2-PH12-R00, LXK2-PH12-S00 LXK2-PL12-P00, LXK2-PL12-Q00, LXK2-PL12-R00    Source: www.luxeon.com   KINGBRIGHT:   KA-3528ASYC Source: www.kingbright.com
footprint U57X32
pins: A, K C

## LEDTOPLED-SANTANA
designator LED?, comment LED   OSRAM: - CHIPLED LG R971, LG N971, LY N971, LG Q971, LY Q971, LO R971, LY R971 LH N974, LH R974 LS Q976, LO Q976, LY Q976 LO Q996 - Hyper CHIPLED LW Q18S LB Q993, LB Q99A, LB R99A - SideLED LS A670, LO A670, LY A670, LG A670, LP A670 LB A673, LV A673, LT A673, LW A673 LH A674 LY A675 LS A676, LA A676, LO A676, LY A676, LW A676 LS A679, LY A679, LG A679 -  Hyper Micro SIDELEDÂ® LS Y876, LA Y876, LO Y876, LY Y876 LT Y87S - SmartLED LW L88C, LW L88S LB L89C, LB L89S, LG L890 LS L89K, LO L89K, LY L89K LS L896, LA L896, LO L896, LY L896 - TOPLED LS T670, LO T670, LY T670, LG T670, LP T670 LSG T670, LSP T670, LSY T670, LOP T670, LYG T670 LG T671, LOG T671, LSG T671 LB T673, LV T673, LT T673, LW T673 LH T674 LS T676, LA T676, LO T676, LY T676, LB T676, LH T676, LSB T676, LW T676 LB T67C, LV T67C, LT T67C, LS T67K, LO T67K, LY T67K, LW E67C LS E67B, LA E67B, LO E67B, LY E67B, LB E67C, LV E67C, LT E67C LW T67C LS T679, LY T679, LG T679 LS T770, LO T770, LY T770, LG T770, LP T770 LB T773, LV T773, LT T773, LW T773 LH T774 LS E675, LA E675, LY E675, LS T675 LS T776, LA T776, LO T776, LY T776, LB T776 LHGB T686 LT T68C, LB T68C - Hyper Mini TOPLEDÂ® LB M676 - Mini TOPLED SantanaÂ® LG M470 LS M47K, LO M47K, LY M47K    Source: http://www.osram.convergy.de   LUXEON: - LUMILEDÂ® LXK2-PW12-R00, LXK2-PW12-S00, LXK2-PW14-U00, LXK2-PW14-V00 LXK2-PM12-R00, LXK2-PM12-S00, LXK2-PM14-U00 LXK2-PE12-Q00, LXK2-PE12-R00, LXK2-PE12-S00, LXK2-PE14-T00, LXK2-PE14-U00 LXK2-PB12-K00, LXK2-PB12-L00, LXK2-PB12-M00, LXK2-PB14-N00, LXK2-PB14-P00, LXK2-PB14-Q00 LXK2-PR12-L00, LXK2-PR12-M00, LXK2-PR14-Q00, LXK2-PR14-R00 LXK2-PD12-Q00, LXK2-PD12-R00, LXK2-PD12-S00 LXK2-PH12-R00, LXK2-PH12-S00 LXK2-PL12-P00, LXK2-PL12-Q00, LXK2-PL12-R00    Source: www.luxeon.com   KINGBRIGHT:   KA-3528ASYC Source: www.kingbright.com
footprint MINI-TOPLED-SANTANA
pins: A, C

## MAG_PULSE_HX1188FNL
designator ?
footprint MAG_PULSE_HX1188FNL
pins: P$1, P$2, P$3, P$6, P$7, P$8, P$9, P$10, P$11, P$14, P$15, P$16

## NX3225GA
designator ?
footprint NDK3.2X2.5
pins: P$1 OSC0, P$2 NC2, P$3 OSC1, P$4 NC4

## R-US_0204/2V
designator R?, comment RESISTOR, American symbol
footprint 0204V
pins: 1, 2

## R-US_0204/5
designator R?, comment RESISTOR, American symbol
footprint 0204/5
pins: 1, 2

## R-US_0204/7
designator R?, comment RESISTOR, American symbol
footprint 0204/7
pins: 1, 2

## R-US_0207/2V
designator R?, comment RESISTOR, American symbol
footprint 0207/2V
pins: 1, 2

## R-US_0207/5V
designator R?, comment RESISTOR, American symbol
footprint 0207/5V
pins: 1, 2

## R-US_0207/7
designator R?, comment RESISTOR, American symbol
footprint 0207/7
pins: 1, 2

## R-US_0207/10
designator R?, comment RESISTOR, American symbol
footprint 0207/10
pins: 1, 2

## R-US_0207/12
designator R?, comment RESISTOR, American symbol
footprint 0207/12
pins: 1, 2

## R-US_0207/15
designator R?, comment RESISTOR, American symbol
footprint 0207/15
pins: 1, 2

## R-US_0309/10
designator R?, comment RESISTOR, American symbol
footprint 0309/10
pins: 1, 2

## R-US_0309/12
designator R?, comment RESISTOR, American symbol
footprint 0309/12
pins: 1, 2

## R-US_0309/V
designator R?, comment RESISTOR, American symbol
footprint 0309V
pins: 1, 2

## R-US_0411/3V
designator R?, comment RESISTOR, American symbol
footprint 0411V
pins: 1, 2

## R-US_0411/12
designator R?, comment RESISTOR, American symbol
footprint 0411/12
pins: 1, 2

## R-US_0411/15
designator R?, comment RESISTOR, American symbol
footprint 0411/15
pins: 1, 2

## R-US_0414/5V
designator R?, comment RESISTOR, American symbol
footprint 0414V
pins: 1, 2

## R-US_0414/15
designator R?, comment RESISTOR, American symbol
footprint 0414/15
pins: 1, 2

## R-US_0613/5V
designator R?, comment RESISTOR, American symbol
footprint P0613V
pins: 1, 2

## R-US_0613/15
designator R?, comment RESISTOR, American symbol
footprint P0613/15
pins: 1, 2

## R-US_0617/5V
designator R?, comment RESISTOR, American symbol
footprint 0617V
pins: 1, 2

## R-US_0617/17
designator R?, comment RESISTOR, American symbol
footprint 0617/17
pins: 1, 2

## R-US_0617/22
designator R?, comment RESISTOR, American symbol
footprint 0617/22
pins: 1, 2

## R-US_0817/7V
designator R?, comment RESISTOR, American symbol
footprint P0817V
pins: 1, 2

## R-US_0817/22
designator R?, comment RESISTOR, American symbol
footprint P0817/22
pins: 1, 2

## R-US_0922/22
designator R?, comment RESISTOR, American symbol
footprint 0922/22
pins: 1, 2

## R-US_0922V
designator R?, comment RESISTOR, American symbol
footprint 0922V
pins: 1, 2

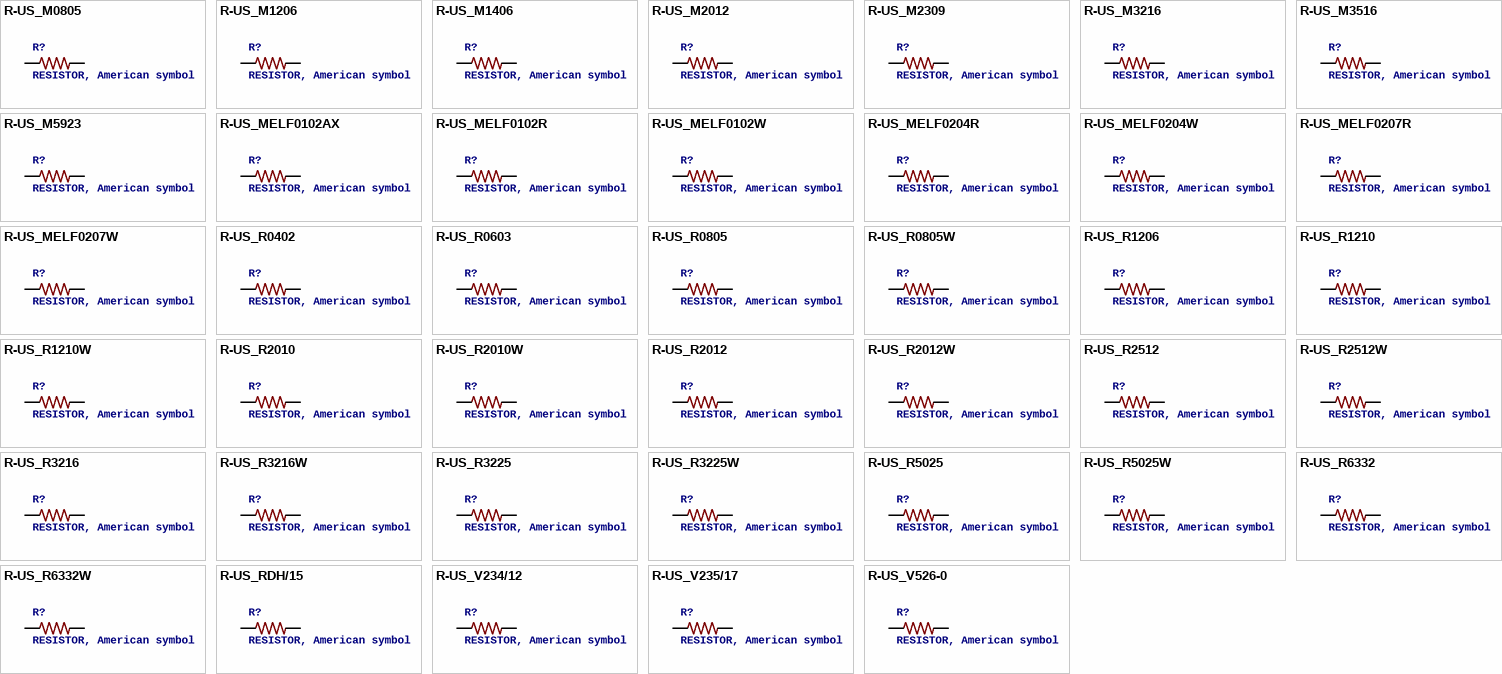
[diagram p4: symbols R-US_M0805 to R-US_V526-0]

## R-US_M0805
designator R?, comment RESISTOR, American symbol
footprint M0805
pins: 1, 2

## R-US_M1206
designator R?, comment RESISTOR, American symbol
footprint M1206
pins: 1, 2

## R-US_M1406
designator R?, comment RESISTOR, American symbol
footprint M1406
pins: 1, 2

## R-US_M2012
designator R?, comment RESISTOR, American symbol
footprint M2012
pins: 1, 2

## R-US_M2309
designator R?, comment RESISTOR, American symbol
footprint M2309
pins: 1, 2

## R-US_M3216
designator R?, comment RESISTOR, American symbol
footprint M3216
pins: 1, 2

## R-US_M3516
designator R?, comment RESISTOR, American symbol
footprint M3516
pins: 1, 2

## R-US_M5923
designator R?, comment RESISTOR, American symbol
footprint M5923
pins: 1, 2

## R-US_MELF0102AX
designator R?, comment RESISTOR, American symbol
footprint MINI_MELF-0102AX
pins: 1, 2

## R-US_MELF0102R
designator R?, comment RESISTOR, American symbol
footprint MINI_MELF-0102R
pins: 1, 2

## R-US_MELF0102W
designator R?, comment RESISTOR, American symbol
footprint MINI_MELF-0102W
pins: 1, 2

## R-US_MELF0204R
designator R?, comment RESISTOR, American symbol
footprint MINI_MELF-0204R
pins: 1, 2

## R-US_MELF0204W
designator R?, comment RESISTOR, American symbol
footprint MINI_MELF-0204W
pins: 1, 2

## R-US_MELF0207R
designator R?, comment RESISTOR, American symbol
footprint MINI_MELF-0207R
pins: 1, 2

## R-US_MELF0207W
designator R?, comment RESISTOR, American symbol
footprint MINI_MELF-0207W
pins: 1, 2

## R-US_R0402
designator R?, comment RESISTOR, American symbol
footprint R0402
pins: 1, 2

## R-US_R0603
designator R?, comment RESISTOR, American symbol
footprint R0603
pins: 1, 2

## R-US_R0805
designator R?, comment RESISTOR, American symbol
footprint R0805
pins: 1, 2

## R-US_R0805W
designator R?, comment RESISTOR, American symbol
footprint R0805W
pins: 1, 2

## R-US_R1206
designator R?, comment RESISTOR, American symbol
footprint R1206
pins: 1, 2

## R-US_R1210
designator R?, comment RESISTOR, American symbol
footprint R1210
pins: 1, 2

## R-US_R1210W
designator R?, comment RESISTOR, American symbol
footprint R1210W
pins: 1, 2

## R-US_R2010
designator R?, comment RESISTOR, American symbol
footprint R2010
pins: 1, 2

## R-US_R2010W
designator R?, comment RESISTOR, American symbol
footprint R2010W
pins: 1, 2

## R-US_R2012
designator R?, comment RESISTOR, American symbol
footprint R2012
pins: 1, 2

## R-US_R2012W
designator R?, comment RESISTOR, American symbol
footprint R2012W
pins: 1, 2

## R-US_R2512
designator R?, comment RESISTOR, American symbol
footprint R2512
pins: 1, 2

## R-US_R2512W
designator R?, comment RESISTOR, American symbol
footprint R2512W
pins: 1, 2

## R-US_R3216
designator R?, comment RESISTOR, American symbol
footprint R3216
pins: 1, 2

## R-US_R3216W
designator R?, comment RESISTOR, American symbol
footprint R3216W
pins: 1, 2

## R-US_R3225
designator R?, comment RESISTOR, American symbol
footprint R3225
pins: 1, 2

## R-US_R3225W
designator R?, comment RESISTOR, American symbol
footprint R3225W
pins: 1, 2

## R-US_R5025
designator R?, comment RESISTOR, American symbol
footprint R5025
pins: 1, 2

## R-US_R5025W
designator R?, comment RESISTOR, American symbol
footprint R5025W
pins: 1, 2

## R-US_R6332
designator R?, comment RESISTOR, American symbol
footprint R6332
pins: 1, 2

## R-US_R6332W
designator R?, comment RESISTOR, American symbol
footprint R6332W
pins: 1, 2

## R-US_RDH/15
designator R?, comment RESISTOR, American symbol
footprint RDH/15
pins: 1, 2

## R-US_V234/12
designator R?, comment RESISTOR, American symbol
footprint V234/12
pins: 1, 2

## R-US_V235/17
designator R?, comment RESISTOR, American symbol
footprint V235/17
pins: 1, 2

## R-US_V526-0
designator R?, comment RESISTOR, American symbol
footprint V526-0
pins: 1, 2

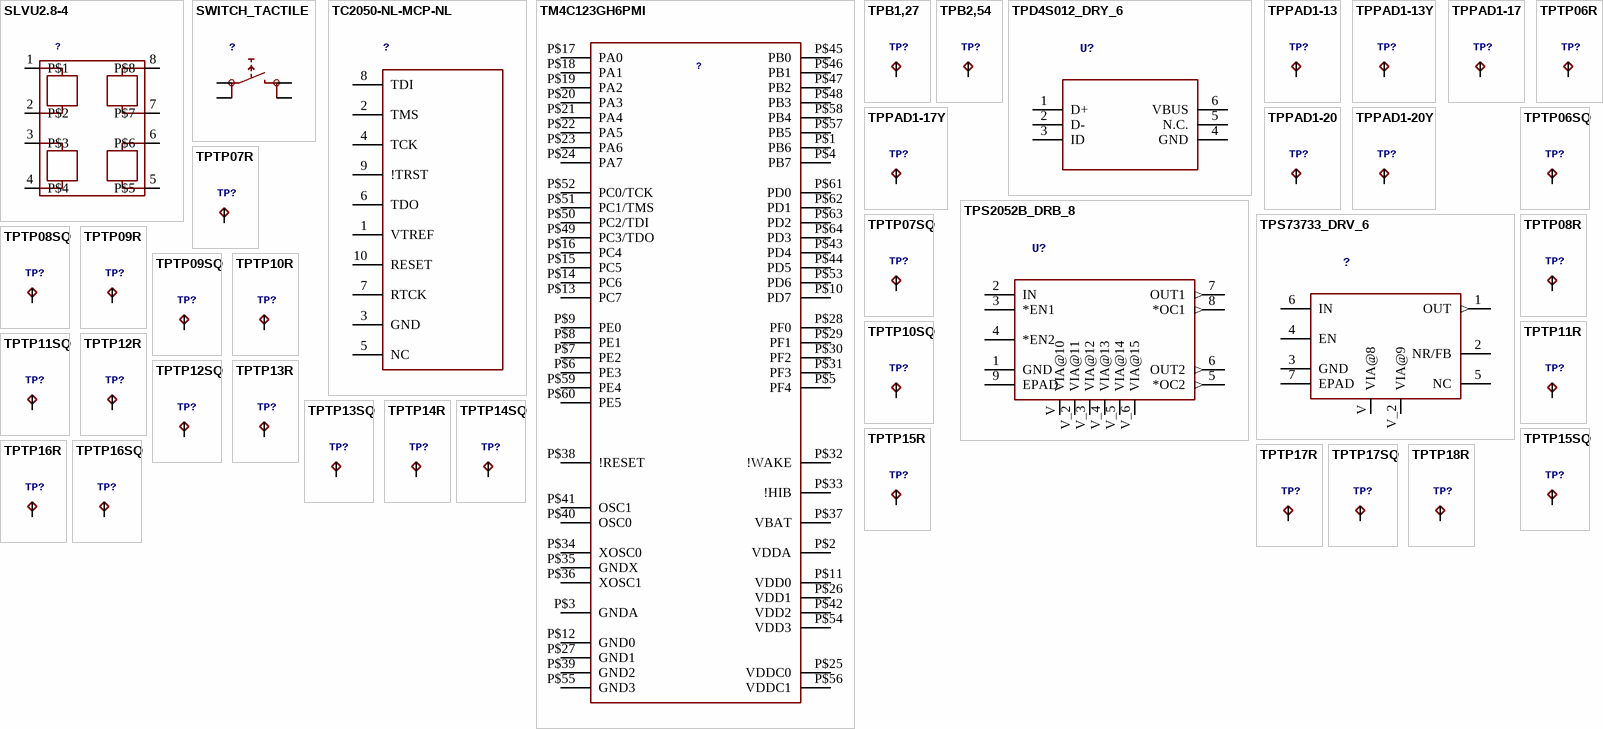
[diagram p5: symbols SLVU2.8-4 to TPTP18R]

## SLVU2.8-4
designator ?
footprint D8
pins: 1 P$1, 2 P$2, 3 P$3, 4 P$4, 5 P$5, 6 P$6, 7 P$7, 8 P$8

## SWITCH_TACTILE
designator ?
footprint SWITCH_6MM_6MM_TE_CON_SMD
pins: P$1 0@A, P$2 0@B, P$3 1@A, P$4 1@B

## TC2050-NL-MCP-NL
designator ?, comment TAG-CONNECT ISP Connector  Manufacturer: Tag-Connect  Cable for easy In-Circuit PCB Programming. Designed for JTAG 10 pin, suitable for many others. Pin Connection for TC2050 NL.    	   PAD	Description	   1	VTREF	   2	TMS	   3	GND	   4	TCK	   5	NC	   6	TDO	   7	RTCK	   8	TDI	   9	!TRST	   10	RESET		  Â©2009 ROFA.cz  Modified 7/2011 by Tim McCarthy-Smith VIDA Products INC  (value not drawn)
footprint TC2030-MCP-NL
pins: 1 VTREF, 2 TMS, 3 GND, 4 TCK, 5 NC, 6 TDO, 7 RTCK, 8 TDI, 9 !TRST, 10 RESET

## TM4C123GH6PMI
designator ?
footprint LQFP-64-PM
pins: P$1 PB6, P$2 VDDA, P$3 GNDA, P$4 PB7, P$5 PF4, P$6 PE3, P$7 PE2, P$8 PE1, P$9 PE0, P$10 PD7, P$11 VDD0, P$12 GND0, P$13 PC7, P$14 PC6, P$15 PC5, P$16 PC4, P$17 PA0, P$18 PA1, P$19 PA2, P$20 PA3, P$21 PA4, P$22 PA5, P$23 PA6, P$24 PA7, P$25 VDDC0, P$26 VDD1, P$27 GND1, P$28 PF0, P$29 PF1, P$30 PF2, P$31 PF3, P$32 !WAKE, P$33 !HIB, P$34 XOSC0, P$35 GNDX, P$36 XOSC1, P$37 VBAT, P$38 !RESET, P$39 GND2, P$40 OSC0, P$41 OSC1, P$42 VDD2, P$43 PD4, P$44 PD5, P$45 PB0, P$46 PB1, P$47 PB2, P$48 PB3, P$49 PC3/TDO, P$50 PC2/TDI, P$51 PC1/TMS, P$52 PC0/TCK, P$53 PD6, P$54 VDD3, P$55 GND3, P$56 VDDC1, P$57 PB5, P$58 PB4, P$59 PE4, P$60 PE5, P$61 PD0, P$62 PD1, P$63 PD2, P$64 PD3

## TPB1,27
designator TP?, comment Test pad  (value not drawn)
footprint B1,27
pins: TP

## TPB2,54
designator TP?, comment Test pad  (value not drawn)
footprint B2,54
pins: TP

## TPD4S012_DRY_6
designator U?
GENERIC_PART_NUMBER: TPD4S012; MANUFACTURER: Texas Instruments; MANUFACTURER_PART_NUMBER: tpd4s012_dry_6; DESCRIPTION: 4-Channel USB ESD Solution with Power Clamp; FAMILY_NAME: ESD Solution; INDUSTRY_STD_PKG_TYPE: SON; PACKAGE_DESIGNATOR: DRY; PIN_COUNT: 6
footprint DRY6
pins: 1 D+, 2 D-, 3 ID, 4 GND (power), 5 N.C., 6 VBUS

## TPPAD1-13
designator TP?, comment Test pad  (value not drawn)
footprint P1-13
pins: TP

## TPPAD1-13Y
designator TP?, comment Test pad  (value not drawn)
footprint P1-13Y
pins: TP

## TPPAD1-17
designator TP?, comment Test pad  (value not drawn)
footprint P1-17
pins: TP

## TPPAD1-17Y
designator TP?, comment Test pad  (value not drawn)
footprint P1-17Y
pins: TP

## TPPAD1-20
designator TP?, comment Test pad  (value not drawn)
footprint P1-20
pins: TP

## TPPAD1-20Y
designator TP?, comment Test pad  (value not drawn)
footprint P1-20Y
pins: TP

## TPS2052B_DRB_8
designator U?
GENERIC_PART_NUMBER: TPS2052B; MANUFACTURER: Texas Instruments; MANUFACTURER_PART_NUMBER: tps2052b_drb_8; DESCRIPTION: Current-Limited, Power-Distribution Switches; FAMILY_NAME: USB POWER SWITCH; INDUSTRY_STD_PKG_TYPE: SON; PACKAGE_DESIGNATOR: DRB; PIN_COUNT: 8
footprint DRB8_2P4X1P65
pins: 1 GND (power), 2 IN, 3 *EN1, 4 *EN2, 5 *OC2 (out), 6 OUT2 (out), 7 OUT1 (out), 8 *OC1 (out), 9 EPAD, V VIA@10, V_2 VIA@11, V_3 VIA@12, V_4 VIA@13, V_5 VIA@14, V_6 VIA@15

## TPS73733_DRV_6
designator ?
footprint DRV6_1P6X1
pins: 1 OUT (out), 2 NR/FB, 3 GND (power), 4 EN, 5 NC, 6 IN, 7 EPAD, V VIA@8, V_2 VIA@9

## TPTP06R
designator TP?, comment Test pad  (value not drawn)
footprint TP06R
pins: TP

## TPTP06SQ
designator TP?, comment Test pad  (value not drawn)
footprint TP06SQ
pins: TP

## TPTP07R
designator TP?, comment Test pad  (value not drawn)
footprint TP07R
pins: TP

## TPTP07SQ
designator TP?, comment Test pad  (value not drawn)
footprint TP07SQ
pins: TP

## TPTP08R
designator TP?, comment Test pad  (value not drawn)
footprint TP08R
pins: TP

## TPTP08SQ
designator TP?, comment Test pad  (value not drawn)
footprint TP08SQ
pins: TP

## TPTP09R
designator TP?, comment Test pad  (value not drawn)
footprint TP09R
pins: TP

## TPTP09SQ
designator TP?, comment Test pad  (value not drawn)
footprint TP09SQ
pins: TP

## TPTP10R
designator TP?, comment Test pad  (value not drawn)
footprint TP10R
pins: TP

## TPTP10SQ
designator TP?, comment Test pad  (value not drawn)
footprint TP10SQ
pins: TP

## TPTP11R
designator TP?, comment Test pad  (value not drawn)
footprint TP11R
pins: TP

## TPTP11SQ
designator TP?, comment Test pad  (value not drawn)
footprint TP11SQ
pins: TP

## TPTP12R
designator TP?, comment Test pad  (value not drawn)
footprint TP12R
pins: TP

## TPTP12SQ
designator TP?, comment Test pad  (value not drawn)
footprint TP12SQ
pins: TP

## TPTP13R
designator TP?, comment Test pad  (value not drawn)
footprint TP13R
pins: TP

## TPTP13SQ
designator TP?, comment Test pad  (value not drawn)
footprint TP13SQ
pins: TP

## TPTP14R
designator TP?, comment Test pad  (value not drawn)
footprint TP14R
pins: TP

## TPTP14SQ
designator TP?, comment Test pad  (value not drawn)
footprint TP14SQ
pins: TP

## TPTP15R
designator TP?, comment Test pad  (value not drawn)
footprint TP15R
pins: TP

## TPTP15SQ
designator TP?, comment Test pad  (value not drawn)
footprint TP15SQ
pins: TP

## TPTP16R
designator TP?, comment Test pad  (value not drawn)
footprint TP16R
pins: TP

## TPTP16SQ
designator TP?, comment Test pad  (value not drawn)
footprint TP16SQ
pins: TP

## TPTP17R
designator TP?, comment Test pad  (value not drawn)
footprint TP17R
pins: TP

## TPTP17SQ
designator TP?, comment Test pad  (value not drawn)
footprint TP17SQ
pins: TP

## TPTP18R
designator TP?, comment Test pad  (value not drawn)
footprint TP18R
pins: TP

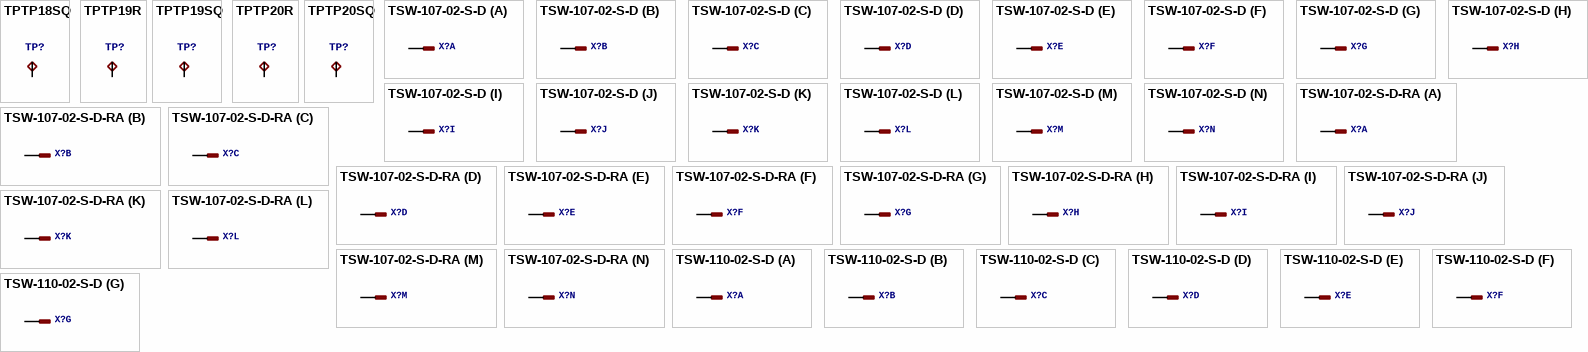
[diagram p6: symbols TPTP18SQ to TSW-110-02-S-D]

## TPTP18SQ
designator TP?, comment Test pad  (value not drawn)
footprint TP18SQ
pins: TP

## TPTP19R
designator TP?, comment Test pad  (value not drawn)
footprint TP19R
pins: TP

## TPTP19SQ
designator TP?, comment Test pad  (value not drawn)
footprint TP19SQ
pins: TP

## TPTP20R
designator TP?, comment Test pad  (value not drawn)
footprint TP20R
pins: TP

## TPTP20SQ
designator TP?, comment Test pad  (value not drawn)
footprint TP20SQ
pins: TP

## TSW-107-02-S-D
designator X?, comment THROUGH-HOLE .025" SQ POST HEADER   Source: Samtec TSW.pdf  (value not drawn)
footprint TSW-107-02-S-D
part A pins: 1
part B pins: 2 1
part C pins: 3 1
part D pins: 4 1
part E pins: 5 1
part F pins: 6 1
part G pins: 7 1
part H pins: 8 1
part I pins: 9 1
part J pins: 10 1
part K pins: 11 1
part L pins: 12 1
part M pins: 13 1
part N pins: 14 1

## TSW-107-02-S-D-RA
designator X?, comment THROUGH-HOLE .025" SQ POST HEADER   Source: Samtec TSW.pdf  (value not drawn)
footprint TSW-107-02-S-D-RA
part A pins: 1
part B pins: 2 1
part C pins: 3 1
part D pins: 4 1
part E pins: 5 1
part F pins: 6 1
part G pins: 7 1
part H pins: 8 1
part I pins: 9 1
part J pins: 10 1
part K pins: 11 1
part L pins: 12 1
part M pins: 13 1
part N pins: 14 1

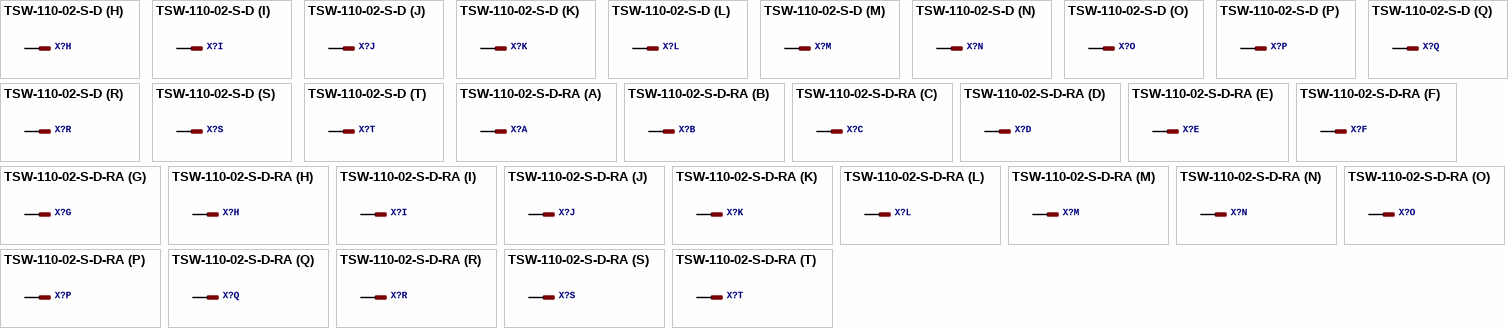
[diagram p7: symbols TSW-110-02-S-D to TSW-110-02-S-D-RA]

## TSW-110-02-S-D
designator X?, comment THROUGH-HOLE .025" SQ POST HEADER   Source: Samtec TSW.pdf  (value not drawn)
footprint TSW-110-02-S-D
part A pins: 1
part B pins: 2 1
part C pins: 3 1
part D pins: 4 1
part E pins: 5 1
part F pins: 6 1
part G pins: 7 1
part H pins: 8 1
part I pins: 9 1
part J pins: 10 1
part K pins: 11 1
part L pins: 12 1
part M pins: 13 1
part N pins: 14 1
part O pins: 15 1
part P pins: 16 1
part Q pins: 17 1
part R pins: 18 1
part S pins: 19 1
part T pins: 20 1

## TSW-110-02-S-D-RA
designator X?, comment THROUGH-HOLE .025" SQ POST HEADER   Source: Samtec TSW.pdf  (value not drawn)
footprint TSW-110-02-S-D-RA
part A pins: 1
part B pins: 2 1
part C pins: 3 1
part D pins: 4 1
part E pins: 5 1
part F pins: 6 1
part G pins: 7 1
part H pins: 8 1
part I pins: 9 1
part J pins: 10 1
part K pins: 11 1
part L pins: 12 1
part M pins: 13 1
part N pins: 14 1
part O pins: 15 1
part P pins: 16 1
part Q pins: 17 1
part R pins: 18 1
part S pins: 19 1
part T pins: 20 1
